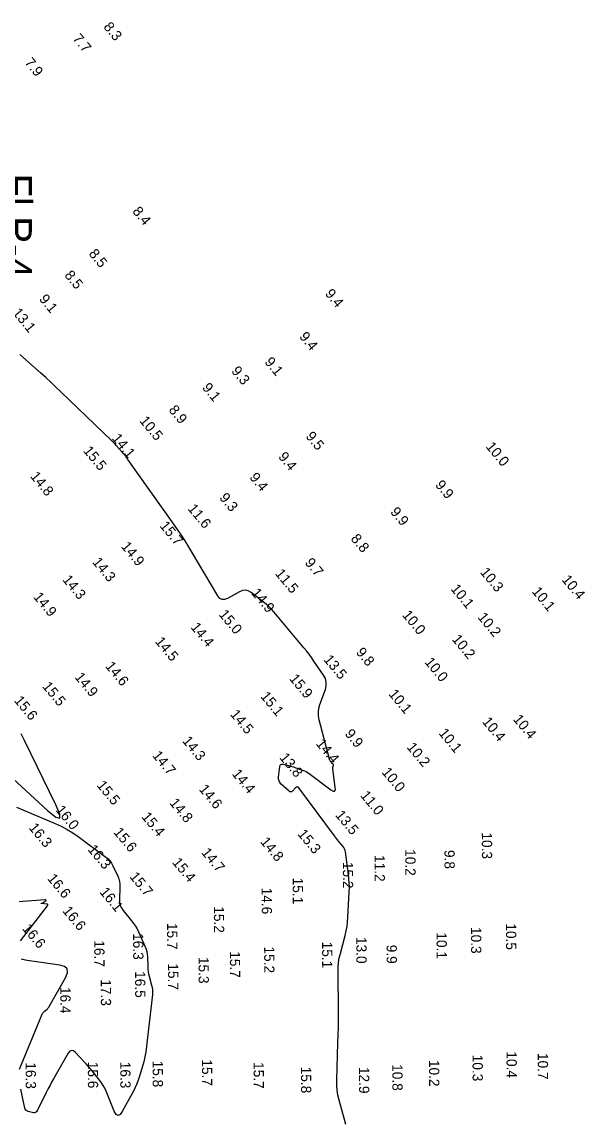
# Model space of a CAD drawing. Extents: x 824616 to 827440, y 158441 to 163197.
# Drawn here: x 826530 to 826805, y 160899 to 161437 of the extents above; entities that cross this region are included whole.
import ezdxf

# ---------------------------------------------------------------- set-up
doc = ezdxf.new("R2010")
doc.units = 0
for name, color, linetype in [('V-CHAN-CONT-EL14', 7, 'Continuous'), ('V-CHAN-CONT-EL16', 7, 'Continuous'), ('V-CHAN-NAID', 7, 'Continuous'), ('V-TOPO-SOUN', 7, 'Continuous')]:
    doc.layers.add(name, color=color, linetype=linetype)

msp = doc.modelspace()

# ---------------------------------------------------------------- linework, layer by layer
at = {"layer": 'V-CHAN-CONT-EL14'}
msp.add_lwpolyline([(826687.95, 160898.64), (826687.35, 160901.03), (826684.63, 160910.56), (826684.05, 160912.96), (826683.66, 160915.38), (826683.46, 160917.82), (826683.45, 160920.29), (826684.08, 160938.48), (826684.19, 160942.34), (826684.27, 160946.2), (826684.3, 160950.06), (826684.28, 160953.92), (826684.12, 160973.36), (826684.17, 160975.62), (826684.38, 160977.85), (826684.73, 160980.06), (826685.24, 160982.25), (826687.57, 160990.99), (826688.09, 160993.18), (826688.5, 160995.39), (826688.79, 160997.62), (826688.96, 160999.87), (826689.59, 161012.22), (826689.65, 161014.35), (826689.61, 161016.47), (826689.47, 161018.59), (826689.22, 161020.71), (826687.69, 161031.81), (826687.53, 161032.58), (826687.26, 161033.31), (826686.9, 161033.99), (826686.43, 161034.63), (826684.35, 161037.07), (826683.84, 161037.69), (826683.33, 161038.31), (826682.84, 161038.95), (826682.35, 161039.59), (826664.88, 161063.06), (826664.54, 161063.41), (826664.17, 161063.54), (826663.8, 161063.46), (826663.4, 161063.16), (826661.81, 161061.54), (826661.4, 161061.23), (826661, 161061.12), (826660.58, 161061.21), (826660.16, 161061.49), (826656.4, 161064.91), (826655.74, 161065.65), (826655.3, 161066.47), (826655.08, 161067.38), (826655.08, 161068.37), (826655.65, 161073.52), (826655.81, 161074.15), (826656.13, 161074.54), (826656.61, 161074.71), (826657.25, 161074.66), (826660.15, 161073.97), (826660.87, 161073.79), (826661.58, 161073.59), (826662.29, 161073.37), (826663, 161073.14), (826666.8, 161071.82), (826667.65, 161071.49), (826668.47, 161071.1), (826669.26, 161070.64), (826670.01, 161070.12), (826680.66, 161062.14), (826681.74, 161061.51), (826682.45, 161061.51), (826682.8, 161062.13), (826682.78, 161063.38), (826681.61, 161072.33), (826681.6, 161072.55), (826681.6, 161072.76), (826681.61, 161072.98), (826681.65, 161073.19), (826681.84, 161074.05), (826681.86, 161074.26), (826681.83, 161074.45), (826681.76, 161074.64), (826681.63, 161074.81), (826680.54, 161076.02), (826680.33, 161076.28), (826680.15, 161076.57), (826680.01, 161076.87), (826679.91, 161077.2), (826674.97, 161096.43), (826674.63, 161098.31), (826674.57, 161100.18), (826674.79, 161102.04), (826675.3, 161103.88), (826677.92, 161111.23), (826678.35, 161113.04), (826678.35, 161114.8), (826677.91, 161116.5), (826677.04, 161118.14), (826672.36, 161125.08), (826671.2, 161126.76), (826669.99, 161128.41), (826668.74, 161130.02), (826667.45, 161131.61), (826652.77, 161149.13), (826651.57, 161150.48), (826650.31, 161151.75), (826648.97, 161152.95), (826647.57, 161154.08), (826641.61, 161158.57), (826640.25, 161159.36), (826638.86, 161159.68), (826637.43, 161159.54), (826635.98, 161158.95), (826630.1, 161155.64), (826628.71, 161155.1), (826627.46, 161155.12), (826626.38, 161155.72), (826625.44, 161156.88), (826613.06, 161177.73), (826610.67, 161181.66), (826608.2, 161185.54), (826605.65, 161189.37), (826603.03, 161193.15), (826581.37, 161223.64), (826581.22, 161223.84), (826581.08, 161224.04), (826580.94, 161224.25), (826580.81, 161224.45), (826580.21, 161225.32), (826580.09, 161225.49), (826579.96, 161225.66), (826579.83, 161225.81), (826579.69, 161225.97), (826579.13, 161226.57), (826578.99, 161226.73), (826578.85, 161226.88), (826578.72, 161227.03), (826578.58, 161227.19), (826575.77, 161230.4), (826575.25, 161230.98), (826574.72, 161231.55), (826574.18, 161232.11), (826573.62, 161232.66), (826548.72, 161256.63), (826546.26, 161258.97), (826543.79, 161261.28), (826541.29, 161263.58), (826538.78, 161265.84), (826528.61, 161274.92)], dxfattribs=at)
at = {"layer": 'V-CHAN-CONT-EL16'}
for points in [[(826516.52, 161075.43), (826542.34, 161051.89), (826546.18, 161048.8), (826548.1, 161048.26), (826548.12, 161050.26), (826546.23, 161054.81), (826530.85, 161086.29), (826529.22, 161089.51)], [(826526.98, 161053.71), (826545.91, 161045.7), (826548.87, 161044.35), (826551.73, 161042.83), (826554.5, 161041.13), (826557.17, 161039.28), (826570.64, 161029.3), (826571.71, 161028.41), (826572.64, 161027.41), (826573.44, 161026.29), (826574.1, 161025.07), (826576.49, 161019.97), (826577.01, 161018.67), (826577.36, 161017.35), (826577.54, 161015.99), (826577.56, 161014.6), (826577.29, 161008.49), (826577.35, 161007.04), (826577.67, 161005.68), (826578.24, 161004.41), (826579.06, 161003.22), (826583.25, 160998.16), (826584.22, 160996.91), (826585.09, 160995.6), (826585.88, 160994.24), (826586.58, 160992.82), (826589.93, 160985.4), (826590.37, 160984.26), (826590.7, 160983.09), (826590.91, 160981.9), (826591, 160980.68), (826591.12, 160975.56), (826591.19, 160974.42), (826591.32, 160973.3), (826591.53, 160972.18), (826591.8, 160971.07), (826593.04, 160966.66), (826593.3, 160965.56), (826593.44, 160964.44), (826593.48, 160963.32), (826593.4, 160962.19), (826590.12, 160934.16), (826589.89, 160932.52), (826589.59, 160930.89), (826589.21, 160929.28), (826588.77, 160927.68), (826586.83, 160921.33), (826586.31, 160919.75), (826585.71, 160918.22), (826585.03, 160916.71), (826584.27, 160915.23), (826578.66, 160904.96), (826577.6, 160903.48), (826576.6, 160903.02), (826575.65, 160903.58), (826574.76, 160905.17), (826570.73, 160914.96), (826570.11, 160916.33), (826569.39, 160917.65), (826568.58, 160918.91), (826567.69, 160920.12), (826563.9, 160924.84), (826562.94, 160926.01), (826561.97, 160927.16), (826560.97, 160928.29), (826559.95, 160929.4), (826555.84, 160933.82), (826554.85, 160934.62), (826553.93, 160934.82), (826553.07, 160934.42), (826552.28, 160933.41), (826545.05, 160920.87), (826544.12, 160919.23), (826543.22, 160917.58), (826542.35, 160915.9), (826541.51, 160914.22), (826537.11, 160905.25), (826536.78, 160904.75), (826536.35, 160904.44), (826535.84, 160904.31), (826535.23, 160904.38), (826532.65, 160905.02), (826532.07, 160905.24), (826531.61, 160905.58), (826531.28, 160906.05), (826531.08, 160906.64), (826529.16, 160915.9)], [(826528.95, 160988.37), (826542.11, 161005.48), (826542.31, 161005.82), (826542.31, 161006.08), (826542.12, 161006.25), (826541.74, 161006.34), (826539.26, 161006.59), (826539.11, 161006.62), (826539.05, 161006.66), (826539.1, 161006.71), (826539.24, 161006.78), (826540.26, 161007.16), (826540.33, 161007.19), (826540.4, 161007.23), (826540.46, 161007.27), (826540.52, 161007.33), (826540.75, 161007.55), (826540.81, 161007.61), (826540.87, 161007.66), (826540.93, 161007.71), (826540.99, 161007.75), (826541.5, 161008.1), (826541.53, 161008.12), (826541.54, 161008.15), (826541.53, 161008.18), (826541.5, 161008.21), (826541.35, 161008.34), (826541.31, 161008.37), (826541.27, 161008.39), (826541.22, 161008.4), (826541.17, 161008.4), (826530.14, 161007.53), (826528.29, 161007.46)], [(826528.42, 160925.58), (826539.55, 160952.48), (826539.74, 160952.87), (826539.97, 160953.23), (826540.24, 160953.55), (826540.56, 160953.85), (826541.92, 160954.96), (826542.24, 160955.25), (826542.53, 160955.56), (826542.8, 160955.91), (826543.03, 160956.28), (826551.07, 160970.67), (826551.95, 160972.93), (826551.75, 160974.66), (826550.49, 160975.86), (826548.16, 160976.52), (826532.21, 160978.72), (826531.45, 160978.84), (826530.7, 160979), (826529.96, 160979.19), (826529.22, 160979.42)]]:
    msp.add_lwpolyline(points, dxfattribs=at)

# ---------------------------------------------------------------- texts
at = {"layer": 'V-CHAN-NAID'}
msp.add_text('Fl R-4', height=14, rotation=270, dxfattribs=at).set_placement((826520.49, 161363.27))
at = {"layer": 'V-TOPO-SOUN'}
for s, rotation, p in [('8.3', 309.7, (826569.21, 161434.85)), ('7.7', 309.7, (826554.19, 161429.08)), ('7.9', 309.7, (826530.66, 161417.38)), ('8.4', 309.7, (826583.38, 161344.67)), ('8.5', 309.7, (826562.02, 161323.98)), ('8.5', 309.7, (826550.15, 161313.45)), ('9.4', 309.7, (826677.48, 161304.46)), ('9.1', 309.7, (826537.77, 161301.83)), ('13.1 ', 309.7, (826524.73, 161295.14)), ('9.4', 309.7, (826664.89, 161283.48)), ('9.1', 309.7, (826647.95, 161271.11)), ('9.3', 309.7, (826631.68, 161266.68)), ('9.1', 309.7, (826617.44, 161258.54)), ('8.9', 309.7, (826601.07, 161247.64)), ('10.5 ', 309.7, (826586.83, 161242.36)), ('14.1 ', 309.7, (826573.37, 161233.78)), ('9.5', 309.7, (826668.03, 161234.75)), ('15.5 ', 309.7, (826559.34, 161227.7)), ('10.0 ', 309.7, (826756.06, 161229.74)), ('9.4', 309.7, (826654.65, 161224.77)), ('14.8 ', 309.7, (826533.41, 161215.22)), ('9.4', 309.7, (826640.59, 161214.67)), ('9.9', 309.7, (826731.33, 161210.99)), ('9.3', 309.7, (826625.86, 161204.75)), ('11.6 ', 309.7, (826610.39, 161199.41)), ('9.9', 309.7, (826709.37, 161197.83)), ('15.7 ', 309.7, (826596.7, 161191.02)), ('8.8', 309.7, (826690.05, 161184.75)), ('14.9 ', 309.7, (826577.84, 161180.98)), ('14.3 ', 309.7, (826563.77, 161173.3)), ('9.7', 309.7, (826667.62, 161172.99)), ('10.3 ', 309.7, (826753.27, 161168.34)), ('14.3 ', 309.7, (826549.19, 161164.71)), ('11.5 ', 309.7, (826653.1, 161167.69)), ('10.4 ', 309.7, (826793.16, 161164.72)), ('14.9 ', 309.7, (826641.42, 161158.21)), ('10.1 ', 309.7, (826738.88, 161160.24)), ('10.1 ', 309.7, (826778.58, 161158.92)), ('14.9 ', 309.7, (826534.95, 161156.29)), ('15.0 ', 309.7, (826625.56, 161147.74)), ('10.0 ', 309.7, (826715.21, 161147.46)), ('14.4 ', 309.7, (826611.83, 161141.5)), ('10.2 ', 309.7, (826752.09, 161146.36)), ('14.5 ', 309.7, (826594.43, 161134.5)), ('10.2 ', 309.7, (826739.5, 161135.61)), ('13.5 ', 309.7, (826676.77, 161125.67)), ('9.8', 309.7, (826692.61, 161129.22)), ('14.6 ', 309.7, (826570.12, 161122.42)), ('10.0 ', 309.7, (826726.15, 161124.45)), ('14.9 ', 309.7, (826555.15, 161117.08)), ('15.9 ', 309.7, (826660.06, 161116.34)), ('15.5 ', 309.7, (826539.35, 161112.55)), ('10.1 ', 309.7, (826708.56, 161108.85)), ('15.6 ', 309.7, (826525.56, 161105.66)), ('15.1 ', 309.7, (826645.91, 161107.69)), ('14.5 ', 309.7, (826631.12, 161098.94)), ('10.4 ', 309.7, (826754.29, 161095.3)), ('10.4 ', 309.7, (826769.37, 161096.52)), ('9.9', 309.7, (826687.13, 161089.4)), ('10.1 ', 309.7, (826733.03, 161089.72)), ('14.3 ', 309.7, (826607.72, 161085.92)), ('14.4 ', 309.7, (826673.03, 161084.58)), ('10.2 ', 309.7, (826717.44, 161082.84)), ('14.7 ', 309.7, (826593.1, 161078.8)), ('13.8 ', 309.7, (826655.25, 161077.77)), ('14.4 ', 309.7, (826632, 161069.84)), ('10.0 ', 309.7, (826705.22, 161070.65)), ('15.5 ', 309.7, (826565.94, 161064.24)), ('14.6 ', 309.7, (826615.88, 161062.33)), ('14.8 ', 309.7, (826601.48, 161055.61)), ('11.0 ', 309.7, (826694.74, 161059.26)), ('16.0 ', 309.7, (826545.84, 161052.13)), ('13.5 ', 309.7, (826682.5, 161049.69)), ('15.4 ', 309.7, (826587.82, 161048.84)), ('16.3 ', 309.7, (826532.7, 161043.51)), ('15.6 ', 309.7, (826574.13, 161041.29)), ('15.3 ', 309.7, (826664.06, 161040.43)), ('14.8 ', 309.7, (826645.85, 161036.66)), ('10.3 ', 270.2, (826754.38, 161041.34)), ('16.3 ', 309.7, (826561.53, 161032.88)), ('14.7 ', 309.7, (826617.07, 161031.38)), ('10.2 ', 270.2, (826716.98, 161033.15)), ('9.8', 270.2, (826736.13, 161032.76)), ('15.4 ', 309.7, (826602.83, 161026.55)), ('15.2 ', 270.2, (826686.47, 161026.94)), ('11.2 ', 270.2, (826701.97, 161030.28)), ('16.6 ', 309.7, (826541.79, 161018.67)), ('15.7 ', 309.7, (826581.95, 161019.59)), ('16.1 ', 309.7, (826567.34, 161012.1)), ('15.1 ', 270.2, (826661.97, 161019.24)), ('14.6 ', 270.2, (826646.81, 161014.34)), ('16.6 ', 309.7, (826549.2, 161002.88)), ('15.2 ', 270.2, (826623.43, 161005.23)), ('16.6 ', 309.7, (826529.51, 160994.21)), ('15.7 ', 270.2, (826600.56, 160997.09)), ('10.3 ', 270.2, (826749.11, 160995.1)), ('10.5 ', 270.2, (826766.18, 160996.9)), ('16.7 ', 270.2, (826564.96, 160988.64)), ('16.3 ', 270.2, (826583.98, 160992.12)), ('15.1 ', 270.2, (826676.32, 160987.94)), ('13.0 ', 270.2, (826693.04, 160990.25)), ('10.1 ', 270.2, (826732.25, 160992.49)), ('15.7 ', 270.2, (826631.26, 160983.28)), ('15.2 ', 270.2, (826648.01, 160985.6)), ('9.9', 270.2, (826707.85, 160986.45)), ('15.7 ', 270.2, (826601.04, 160977.35)), ('15.3 ', 270.2, (826615.94, 160980.5)), ('16.5 ', 270.2, (826584.94, 160973.54)), ('17.3 ', 270.2, (826568.18, 160969.57)), ('16.4 ', 270.2, (826548.38, 160965.83)), ('10.4 ', 270.2, (826766.45, 160934.34)), ('16.3 ', 270.2, (826531.48, 160929.01)), ('15.6 ', 270.2, (826561.85, 160929.26)), ('16.3 ', 270.2, (826577.7, 160929.28)), ('15.8 ', 270.2, (826593.53, 160929.83)), ('15.7 ', 270.2, (826617.61, 160930.44)), ('15.7 ', 270.2, (826642.84, 160929.1)), ('10.2 ', 270.2, (826728.59, 160930.18)), ('10.3 ', 270.2, (826749.83, 160932.71)), ('10.7 ', 270.2, (826781.72, 160933.55)), ('15.8 ', 270.2, (826666, 160926.86)), ('12.9 ', 270.2, (826694.36, 160926.75)), ('10.8 ', 270.2, (826710.63, 160928.09))]:
    msp.add_text(s, height=5, rotation=rotation, dxfattribs=at).set_placement(p)

doc.saveas('drawing.dxf')
